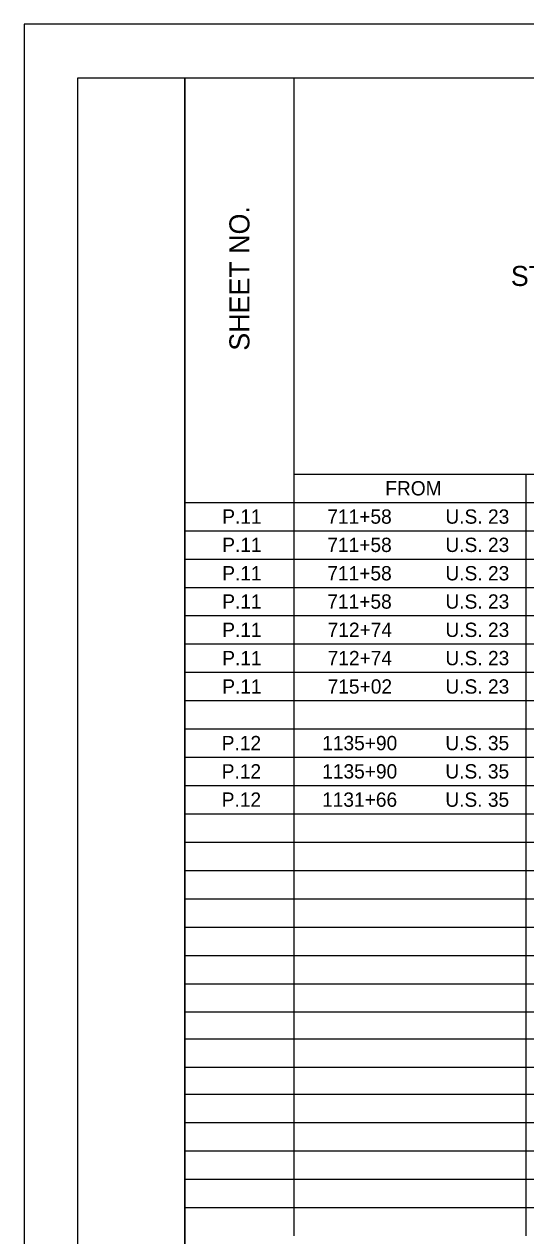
# Model space of a CAD drawing. Extents: x 0 to 34, y 0 to 22.
# Drawn here: x 0 to 4.68, y 10.69 to 22 of the extents above; entities that cross this region are included whole.
import ezdxf

# ---------------------------------------------------------------- set-up
doc = ezdxf.new("R2010")
doc.units = 0
for name, color, linetype in [('SH_Border', 7, 'Continuous'), ('SH_Cut_Line', 7, 'Continuous'), ('SH_Text', 7, 'Continuous')]:
    doc.layers.add(name, color=color, linetype=linetype)

msp = doc.modelspace()

# ---------------------------------------------------------------- linework, layer by layer
at = {"layer": 'SH_Border'}
for points in [[(0.5, 21.5), (1.5, 21.5), (1.5, 0.5), (0.5, 0.5)], [(1.5, 21.5), (33.5, 21.5), (33.5, 0.5), (1.5, 0.5)]]:
    msp.add_lwpolyline(points, close=True, dxfattribs=at)
at = {"layer": 'SH_Cut_Line'}
msp.add_lwpolyline([(0, 0), (34, 0), (34, 22), (0, 22)], close=True, dxfattribs=at)
at = {"layer": 'SH_Text'}
for p, q in [((1.5, 21.5), (2.519, 21.5)), ((1.5, 21.5), (1.5, 21.236)), ((2.519, 21.5), (4.683, 21.5)), ((2.519, 21.5), (2.519, 21.236)), ((4.683, 21.5), (11.918, 21.5)), ((1.5, 21.236), (1.5, 20.972)), ((2.519, 21.236), (2.519, 20.972)), ((1.5, 20.972), (1.5, 20.707)), ((2.519, 20.972), (2.519, 20.707)), ((1.5, 20.707), (1.5, 20.443)), ((2.519, 20.707), (2.519, 20.443)), ((1.5, 20.443), (1.5, 20.179)), ((2.519, 20.443), (2.519, 20.179)), ((1.5, 20.179), (1.5, 19.915)), ((2.519, 20.179), (2.519, 19.915)), ((1.5, 19.915), (1.5, 19.651)), ((2.519, 19.915), (2.519, 19.651)), ((1.5, 19.651), (1.5, 19.386)), ((2.519, 19.651), (2.519, 19.386)), ((1.5, 19.386), (1.5, 19.122)), ((2.519, 19.386), (2.519, 19.122)), ((1.5, 19.122), (1.5, 18.858)), ((2.519, 19.122), (2.519, 18.858)), ((1.5, 18.858), (1.5, 18.594)), ((2.519, 18.858), (2.519, 18.594)), ((1.5, 18.594), (1.5, 18.329)), ((2.519, 18.594), (2.519, 18.329)), ((1.5, 18.329), (1.5, 18.065)), ((2.519, 18.329), (2.519, 18.065)), ((1.5, 18.065), (1.5, 17.801)), ((2.519, 18.065), (2.519, 17.801)), ((1.5, 17.801), (1.5, 17.537)), ((2.519, 17.801), (4.683, 17.801)), ((2.519, 17.801), (2.519, 17.537)), ((4.683, 17.801), (7.451, 17.801)), ((4.683, 17.801), (4.683, 17.537)), ((1.5, 17.537), (2.519, 17.537)), ((1.5, 17.537), (1.5, 17.273)), ((2.519, 17.537), (4.683, 17.537)), ((2.519, 17.537), (2.519, 17.273)), ((4.683, 17.537), (11.918, 17.537)), ((4.683, 17.537), (4.683, 17.273)), ((1.5, 17.273), (2.519, 17.273)), ((1.5, 17.273), (1.5, 17.008)), ((2.519, 17.273), (4.683, 17.273)), ((2.519, 17.273), (2.519, 17.008)), ((4.683, 17.273), (11.918, 17.273)), ((4.683, 17.273), (4.683, 17.008)), ((1.5, 17.008), (2.519, 17.008)), ((1.5, 17.008), (1.5, 16.744)), ((2.519, 17.008), (4.683, 17.008)), ((2.519, 17.008), (2.519, 16.744)), ((4.683, 17.008), (11.918, 17.008)), ((4.683, 17.008), (4.683, 16.744)), ((1.5, 16.744), (2.519, 16.744)), ((1.5, 16.744), (1.5, 16.48)), ((2.519, 16.744), (4.683, 16.744)), ((2.519, 16.744), (2.519, 16.48)), ((4.683, 16.744), (11.918, 16.744)), ((4.683, 16.744), (4.683, 16.48)), ((1.5, 16.48), (2.519, 16.48)), ((1.5, 16.48), (1.5, 16.216)), ((2.519, 16.48), (4.683, 16.48)), ((2.519, 16.48), (2.519, 16.216)), ((4.683, 16.48), (11.918, 16.48)), ((4.683, 16.48), (4.683, 16.216)), ((1.5, 16.216), (2.519, 16.216)), ((1.5, 16.216), (1.5, 15.951)), ((2.519, 16.216), (4.683, 16.216)), ((2.519, 16.216), (2.519, 15.951)), ((4.683, 16.216), (11.918, 16.216)), ((4.683, 16.216), (4.683, 15.951)), ((1.5, 15.951), (2.519, 15.951)), ((1.5, 15.951), (1.5, 15.687)), ((2.519, 15.951), (4.683, 15.951)), ((2.519, 15.951), (2.519, 15.687)), ((4.683, 15.951), (11.918, 15.951)), ((4.683, 15.951), (4.683, 15.687)), ((1.5, 15.687), (2.519, 15.687)), ((1.5, 15.687), (1.5, 15.423)), ((2.519, 15.687), (4.683, 15.687)), ((2.519, 15.687), (2.519, 15.423)), ((4.683, 15.687), (11.918, 15.687)), ((4.683, 15.687), (4.683, 15.423)), ((1.5, 15.423), (2.519, 15.423)), ((1.5, 15.423), (1.5, 15.159)), ((2.519, 15.423), (4.683, 15.423)), ((2.519, 15.423), (2.519, 15.159)), ((4.683, 15.423), (11.918, 15.423)), ((4.683, 15.423), (4.683, 15.159)), ((1.5, 15.159), (2.519, 15.159)), ((1.5, 15.159), (1.5, 14.895)), ((2.519, 15.159), (4.683, 15.159)), ((2.519, 15.159), (2.519, 14.895)), ((4.683, 15.159), (11.918, 15.159)), ((4.683, 15.159), (4.683, 14.895)), ((1.5, 14.895), (2.519, 14.895)), ((1.5, 14.895), (1.5, 14.63)), ((2.519, 14.895), (4.683, 14.895)), ((2.519, 14.895), (2.519, 14.63)), ((4.683, 14.895), (11.918, 14.895)), ((4.683, 14.895), (4.683, 14.63)), ((1.5, 14.63), (2.519, 14.63)), ((1.5, 14.63), (1.5, 14.366)), ((2.519, 14.63), (4.683, 14.63)), ((2.519, 14.63), (2.519, 14.366)), ((4.683, 14.63), (11.918, 14.63)), ((4.683, 14.63), (4.683, 14.366)), ((1.5, 14.366), (2.519, 14.366)), ((1.5, 14.366), (1.5, 14.102)), ((2.519, 14.366), (4.683, 14.366)), ((2.519, 14.366), (2.519, 14.102)), ((4.683, 14.366), (11.918, 14.366)), ((4.683, 14.366), (4.683, 14.102)), ((1.5, 14.102), (2.519, 14.102)), ((1.5, 14.102), (1.5, 13.838)), ((2.519, 14.102), (4.683, 14.102)), ((2.519, 14.102), (2.519, 13.838)), ((4.683, 14.102), (11.918, 14.102)), ((4.683, 14.102), (4.683, 13.838)), ((1.5, 13.838), (2.519, 13.838)), ((1.5, 13.838), (1.5, 13.573)), ((2.519, 13.838), (4.683, 13.838)), ((2.519, 13.838), (2.519, 13.573)), ((4.683, 13.838), (11.918, 13.838)), ((4.683, 13.838), (4.683, 13.573)), ((1.5, 13.573), (2.519, 13.573)), ((1.5, 13.573), (1.5, 13.309)), ((2.519, 13.573), (4.683, 13.573)), ((2.519, 13.573), (2.519, 13.309)), ((4.683, 13.573), (11.918, 13.573)), ((4.683, 13.573), (4.683, 13.309)), ((1.5, 13.309), (2.519, 13.309)), ((1.5, 13.309), (1.5, 13.045)), ((2.519, 13.309), (4.683, 13.309)), ((2.519, 13.309), (2.519, 13.045)), ((4.683, 13.309), (11.918, 13.309)), ((4.683, 13.309), (4.683, 13.045)), ((1.5, 13.045), (2.519, 13.045)), ((1.5, 13.045), (1.5, 12.781)), ((2.519, 13.045), (4.683, 13.045)), ((2.519, 13.045), (2.519, 12.781)), ((4.683, 13.045), (11.918, 13.045)), ((4.683, 13.045), (4.683, 12.781)), ((1.5, 12.781), (2.519, 12.781)), ((1.5, 12.781), (1.5, 12.265)), ((2.519, 12.781), (4.683, 12.781)), ((2.519, 12.781), (2.519, 12.265)), ((4.683, 12.781), (11.918, 12.781)), ((4.683, 12.781), (4.683, 12.265)), ((1.5, 12.529), (2.519, 12.529)), ((2.519, 12.529), (4.683, 12.529)), ((4.683, 12.529), (11.918, 12.529)), ((1.5, 12.265), (2.519, 12.265)), ((1.5, 12.265), (1.5, 11.749)), ((2.519, 12.265), (4.683, 12.265)), ((2.519, 12.265), (2.519, 11.749)), ((4.683, 12.265), (11.918, 12.265)), ((4.683, 12.265), (4.683, 11.749)), ((1.5, 12.013), (2.519, 12.013)), ((2.519, 12.013), (4.683, 12.013)), ((4.683, 12.013), (11.918, 12.013)), ((1.5, 11.749), (2.519, 11.749)), ((1.5, 11.749), (1.5, 11.485)), ((2.519, 11.749), (4.683, 11.749)), ((2.519, 11.749), (2.519, 11.485)), ((4.683, 11.749), (11.918, 11.749)), ((4.683, 11.749), (4.683, 11.485)), ((1.5, 11.485), (2.519, 11.485)), ((1.5, 11.485), (1.5, 11.221)), ((2.519, 11.485), (4.683, 11.485)), ((2.519, 11.485), (2.519, 11.221)), ((4.683, 11.485), (11.918, 11.485)), ((4.683, 11.485), (4.683, 11.221)), ((1.5, 11.221), (2.519, 11.221)), ((1.5, 11.221), (1.5, 10.956)), ((2.519, 11.221), (4.683, 11.221)), ((2.519, 11.221), (2.519, 10.956)), ((4.683, 11.221), (11.918, 11.221)), ((4.683, 11.221), (4.683, 10.956)), ((1.5, 10.956), (2.519, 10.956)), ((1.5, 10.956), (1.5, 10.692)), ((2.519, 10.956), (4.683, 10.956)), ((2.519, 10.956), (2.519, 10.692)), ((4.683, 10.956), (11.918, 10.956)), ((4.683, 10.956), (4.683, 10.692))]:
    msp.add_line(p, q, dxfattribs=at)

# ---------------------------------------------------------------- texts
msp.add_text('SHEET NO.', height=0.1872, rotation=90, dxfattribs=at).set_placement((2.103, 18.953))
for s, height, p in [('STATION', 0.1872, (4.544, 19.557)), ('FROM', 0.1337, (3.371, 17.602)), ('P.11', 0.1337, (1.849, 17.338)), ('711+58', 0.1337, (2.83, 17.338)), ('U.S. 23', 0.1337, (3.933, 17.338)), ('P.11', 0.1337, (1.849, 17.074)), ('711+58', 0.1337, (2.83, 17.074)), ('U.S. 23', 0.1337, (3.933, 17.074)), ('P.11', 0.1337, (1.849, 16.809)), ('711+58', 0.1337, (2.83, 16.809)), ('U.S. 23', 0.1337, (3.933, 16.809)), ('P.11', 0.1337, (1.849, 16.545)), ('711+58', 0.1337, (2.83, 16.545)), ('U.S. 23', 0.1337, (3.933, 16.545)), ('P.11', 0.1337, (1.849, 16.281)), ('712+74', 0.1337, (2.833, 16.281)), ('U.S. 23', 0.1337, (3.933, 16.281)), ('P.11', 0.1337, (1.849, 16.017)), ('712+74', 0.1337, (2.833, 16.017)), ('U.S. 23', 0.1337, (3.933, 16.017)), ('P.11', 0.1337, (1.849, 15.752)), ('715+02', 0.1337, (2.833, 15.752)), ('U.S. 23', 0.1337, (3.933, 15.752)), ('P.12', 0.1337, (1.844, 15.224)), ('1135+90', 0.1337, (2.782, 15.224)), ('U.S. 35', 0.1337, (3.932, 15.224)), ('P.12', 0.1337, (1.844, 14.96)), ('1135+90', 0.1337, (2.782, 14.96)), ('U.S. 35', 0.1337, (3.932, 14.96)), ('P.12', 0.1337, (1.844, 14.696)), ('1131+66', 0.1337, (2.781, 14.696)), ('U.S. 35', 0.1337, (3.932, 14.696))]:
    msp.add_text(s, height=height, dxfattribs=at).set_placement(p)

doc.saveas('drawing.dxf')
